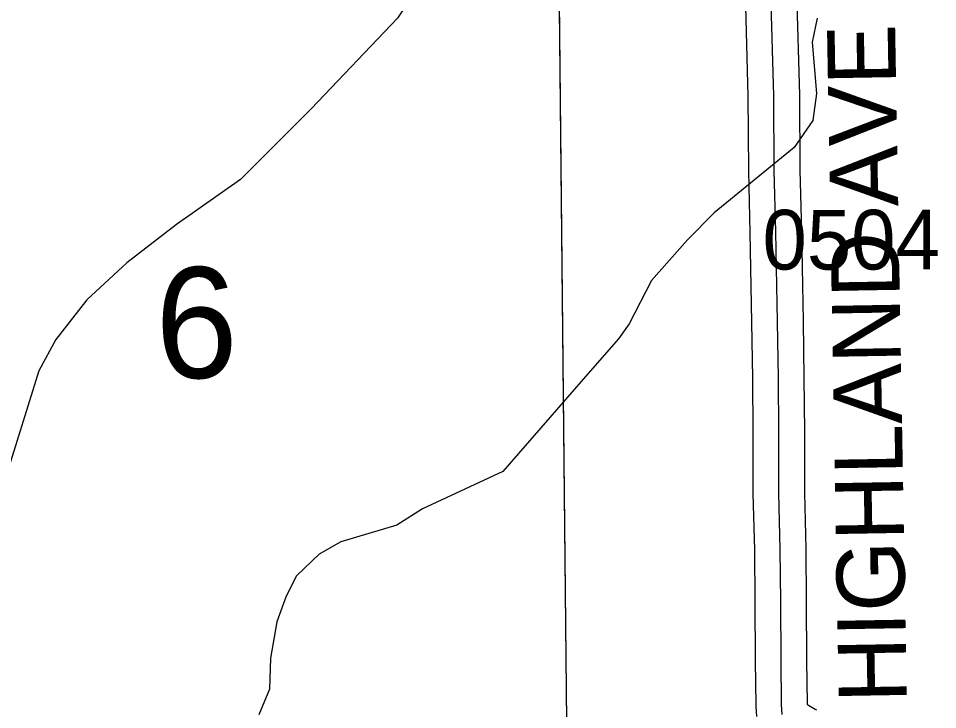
# Model space of a CAD drawing. Extents: x 23.6 to 68.7, y -63 to -29.
# Drawn here: x 39.02 to 40.099, y -46.611 to -45.8 of the extents above; entities that cross this region are included whole.
import ezdxf

# ---------------------------------------------------------------- set-up
doc = ezdxf.new("R2010")
doc.units = 0
for name, color, linetype in [('tdCoHydroRiver', 7, 'Continuous'), ('tdCoSecRdNmbr', 7, 'Continuous'), ('tdCoSecRdTxt', 7, 'Continuous'), ('tdCoSecRteBand', 7, 'Continuous'), ('tdCoSecRteCL', 7, 'Continuous'), ('tdCoSectLine', 7, 'Continuous'), ('tdCoSectLinePart', 7, 'Continuous'), ('tdCoSectNmbr', 7, 'Continuous'), ('tdCoSurfEarth', 7, 'Continuous')]:
    doc.layers.add(name, color=color, linetype=linetype)

msp = doc.modelspace()

# ---------------------------------------------------------------- linework, layer by layer
at = {"layer": 'tdCoHydroRiver'}
for points in [[(39.4209, -45.4382), (39.4291, -45.4744), (39.4365, -45.5895), (39.4412, -45.5911), (39.4413, -45.6005), (39.4638, -45.643), (39.4687, -45.6603), (39.4768, -45.676), (39.4962, -45.7279), (39.4887, -45.7643), (39.4653, -45.7992), (39.3637, -45.9059), (39.2808, -45.9888), (39.2056, -46.0416), (39.1476, -46.0864), (39.1004, -46.1299), (39.0643, -46.1764), (39.044, -46.2132), (39.0053, -46.3376), (38.9976, -46.3806), (38.9913, -46.3838)], [(39.9578, -45.7993), (39.9518, -45.8277), (39.9571, -45.8877), (39.9526, -45.9193), (39.9308, -45.9511), (39.8369, -46.0277), (39.8056, -46.0596), (39.7634, -46.1074), (39.7371, -46.1581), (39.7246, -46.1756), (39.6887, -46.217), (39.5887, -46.3316), (39.4944, -46.3751), (39.4646, -46.3943), (39.3985, -46.4139), (39.3734, -46.4284), (39.3468, -46.4539), (39.3344, -46.4777), (39.3236, -46.5078), (39.3162, -46.5504), (39.3149, -46.5868), (39.3026, -46.6169)]]:
    msp.add_lwpolyline(points, dxfattribs=at)
at = {"layer": 'tdCoSecRteBand'}
for points in [[(39.8869, -46.6189), (39.8861, -46.6072), (39.8861, -46.6064), (39.8861, -46.6055), (39.8854, -46.5541), (39.8854, -46.5539), (39.8854, -46.5538), (39.8851, -46.4845), (39.8846, -46.4235), (39.8828, -46.3575), (39.8828, -46.3571), (39.8828, -46.3566), (39.8829, -46.2853), (39.8823, -46.2223), (39.8813, -46.1562), (39.8793, -46.0508), (39.8775, -45.979), (39.8775, -45.9787), (39.8775, -45.9784), (39.877, -45.891), (39.8736, -45.7695)], [(39.9336, -45.7682), (39.937, -45.8896), (39.937, -45.89), (39.937, -45.8903), (39.9375, -45.9778), (39.9393, -46.0493), (39.9393, -46.0494), (39.9393, -46.0495), (39.9413, -46.1551), (39.9413, -46.1551), (39.9413, -46.1552), (39.9423, -46.2215), (39.9423, -46.2215), (39.9423, -46.2216), (39.9429, -46.2849), (39.9429, -46.2851), (39.9429, -46.2853), (39.9428, -46.3563), (39.9446, -46.4222), (39.9446, -46.4224), (39.9446, -46.4227), (39.9451, -46.4841), (39.9451, -46.4841), (39.9451, -46.4842), (39.9454, -46.5534), (39.946, -46.6039), (39.9461, -46.605), (39.9476, -46.6059), (39.9555, -46.6104), (39.9569, -46.6111)]]:
    msp.add_lwpolyline(points, dxfattribs=at)
at = {"layer": 'tdCoSecRteCL'}
msp.add_lwpolyline([(39.9169, -46.6168), (39.9161, -46.6051), (39.9154, -46.5537), (39.9151, -46.4843), (39.9146, -46.423), (39.9128, -46.3567), (39.9129, -46.2852), (39.9123, -46.2219), (39.9113, -46.1556), (39.9093, -46.0501), (39.9075, -45.9783), (39.907, -45.8905), (39.9036, -45.7686), (39.9036, -45.7558), (39.9019, -45.7002), (39.9008, -45.6691)], dxfattribs=at)
at = {"layer": 'tdCoSectLine'}
msp.add_lwpolyline([(39.6539, -45.6718), (39.6637, -46.6255)], dxfattribs=at)
at = {"layer": 'tdCoSectLinePart'}
msp.add_lwpolyline([(39.6542, -45.7017), (39.6637, -46.6255)], dxfattribs=at)
at = {"layer": 'tdCoSurfEarth'}
msp.add_lwpolyline([(39.9169, -46.6168), (39.9161, -46.6051), (39.9154, -46.5537), (39.9151, -46.4843), (39.9146, -46.423), (39.9128, -46.3567), (39.9129, -46.2852), (39.9123, -46.2219), (39.9113, -46.1556), (39.9093, -46.0501), (39.9075, -45.9783), (39.907, -45.8905), (39.9036, -45.7686), (39.9036, -45.7558), (39.9019, -45.7002), (39.9008, -45.6691)], dxfattribs=at)

# ---------------------------------------------------------------- texts
at = {"layer": 'tdCoSecRdNmbr'}
msp.add_text('0504', height=0.07, rotation=0.0313, dxfattribs=at).set_placement((39.8937, -46.0944))
at = {"layer": 'tdCoSecRdTxt'}
msp.add_text('HIGHLAND AVE', height=0.08, rotation=91, dxfattribs=at).set_placement((40.0632, -46.6024))
at = {"layer": 'tdCoSectNmbr'}
msp.add_text('6', height=0.13, rotation=1.0307, dxfattribs=at).set_placement((39.1819, -46.2226))

doc.saveas('drawing.dxf')
